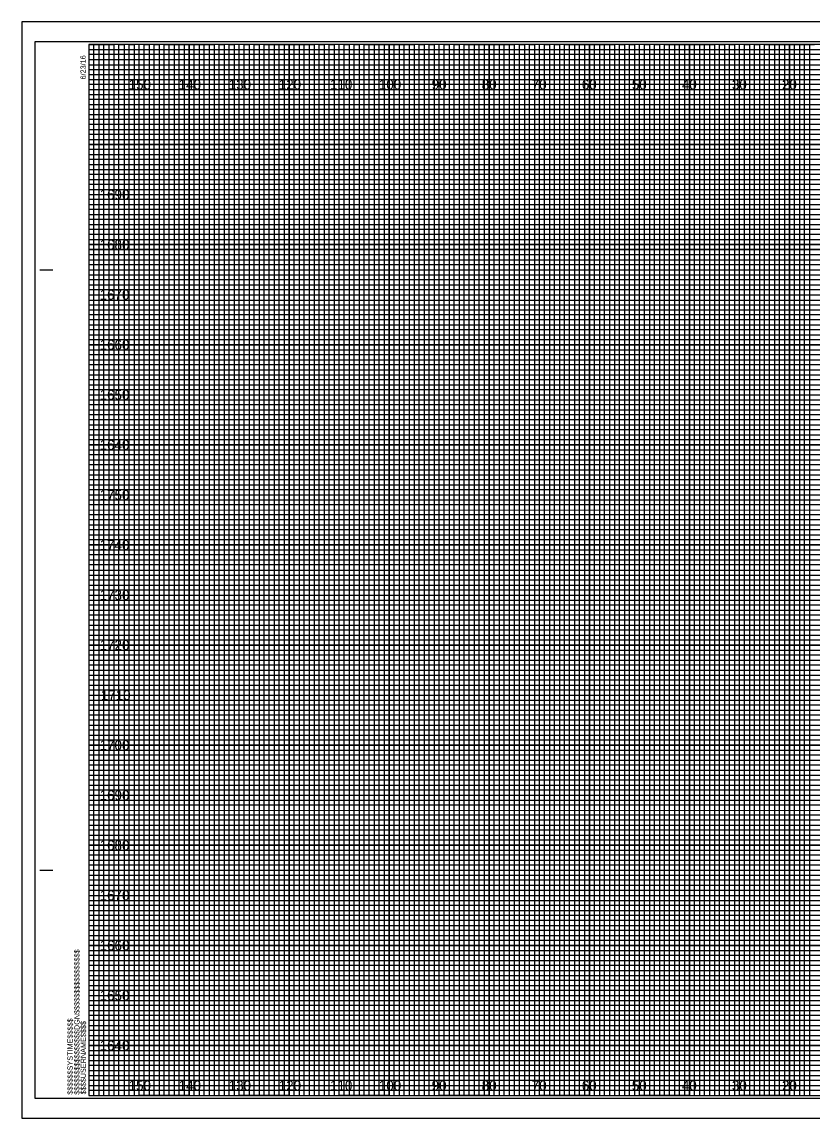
# Model space of a CAD drawing. Extents: x -13 to 323, y 655 to 874.
# Drawn here: x -13.4 to 144.5, y 655.5 to 874.5 of the extents above; entities that cross this region are included whole.
import ezdxf

# ---------------------------------------------------------------- set-up
doc = ezdxf.new("R2010")
doc.units = 0
for name, color, linetype in [('Exist Cross Section Cell', 7, 'Continuous'), ('Exist XS Center Line Elevation Label', 7, 'Continuous'), ('Exist XS Ground Line', 7, 'Continuous'), ('Prop XS Dump Level', 7, 'Continuous'), ('Prop XS Finish Grade', 7, 'Continuous'), ('Prop XS Finish Grade Earthwork', 7, 'Continuous'), ('Prop XS Pvmt Edge Slope', 7, 'Continuous'), ('Prop XS SE Text', 7, 'Continuous'), ('Prop XS SS Elevation Text', 7, 'Continuous'), ('Prop XS Subgrade Earthwork', 7, 'Continuous'), ('Scratch_Level_5', 7, 'Continuous')]:
    doc.layers.add(name, color=color, linetype=linetype)

msp = doc.modelspace()

# ---------------------------------------------------------------- linework, layer by layer
at = {"layer": 'Exist Cross Section Cell'}
for points in [[(0, 870), (5, 870), (5, 660), (15, 660), (15, 870), (25, 870), (25, 660), (35, 660), (35, 870), (45, 870), (45, 660), (55, 660), (55, 870), (65, 870), (65, 660), (75, 660), (75, 870), (85, 870), (85, 660), (95, 660), (95, 870), (105, 870), (105, 660), (115, 660), (115, 870), (125, 870), (125, 660), (135, 660), (135, 870), (145, 870)], [(0, 865), (275, 865)], [(0, 845), (320, 845), (320, 855), (0, 855)], [(0, 825), (320, 825), (320, 835), (0, 835)], [(0, 805), (320, 805), (320, 815), (0, 815)], [(0, 785), (320, 785), (320, 795), (0, 795)], [(0, 765), (320, 765), (320, 775), (0, 775)], [(0, 745), (320, 745), (320, 755), (0, 755)], [(0, 725), (320, 725), (320, 735), (0, 735)], [(0, 705), (320, 705), (320, 715), (0, 715)], [(0, 685), (320, 685), (320, 695), (0, 695)], [(0, 665), (320, 665), (320, 675), (0, 675)]]:
    msp.add_lwpolyline(points, dxfattribs=at)
at = {"layer": 'Exist XS Center Line Elevation Label'}
for p, q in [((10, 870), (0, 870)), ((10, 660), (10, 870)), ((30, 870), (20, 870)), ((20, 870), (20, 660)), ((30, 660), (30, 870)), ((50, 870), (40, 870)), ((40, 870), (40, 660)), ((50, 660), (50, 870)), ((70, 870), (60, 870)), ((60, 870), (60, 660)), ((70, 660), (70, 870)), ((90, 870), (80, 870)), ((80, 870), (80, 660)), ((90, 660), (90, 870)), ((110, 870), (100, 870)), ((100, 870), (100, 660)), ((110, 660), (110, 870)), ((130, 870), (120, 870)), ((120, 870), (120, 660)), ((130, 660), (130, 870)), ((150, 870), (140, 870)), ((140, 870), (140, 660)), ((20, 660), (10, 660)), ((40, 660), (30, 660)), ((60, 660), (50, 660)), ((80, 660), (70, 660)), ((100, 660), (90, 660)), ((120, 660), (110, 660)), ((140, 660), (130, 660))]:
    msp.add_line(p, q, dxfattribs=at)
for points in [[(0, 860), (320, 860), (320, 850), (0, 850)], [(0, 840), (320, 840), (320, 830), (0, 830)], [(0, 820), (320, 820), (320, 810), (0, 810)], [(0, 800), (320, 800), (320, 790), (0, 790)], [(0, 780), (320, 780), (320, 770), (0, 770)], [(0, 760), (320, 760), (320, 750), (0, 750)], [(0, 740), (320, 740), (320, 730), (0, 730)], [(0, 720), (320, 720), (320, 710), (0, 710)], [(0, 700), (320, 700), (320, 690), (0, 690)], [(0, 680), (320, 680), (320, 670), (0, 670)]]:
    msp.add_lwpolyline(points, dxfattribs=at)
at = {"layer": 'Prop XS Dump Level'}
for p, q in [((-9.8, 825), (-7.3, 825)), ((-9.7, 825), (-7.2, 825)), ((-9.8, 705), (-7.3, 705)), ((-9.7, 705), (-7.2, 705)), ((0, 660), (0, 660)), ((0, 660), (0, 660)), ((0, 660), (0, 660)), ((0, 660), (0, 660)), ((0, 660), (0, 660)), ((0, 660), (0, 660)), ((0, 660), (0, 660))]:
    msp.add_line(p, q, dxfattribs=at)
msp.add_lwpolyline([(320, 870), (0, 870), (0, 660), (320, 660)], close=True, dxfattribs=at)
at = {"layer": 'Prop XS Finish Grade'}
for p, q in [((323.3, 874.5), (-13.4, 874.5)), ((-13.4, 874.5), (-13.4, 655.5)), ((-13.4, 655.5), (323.3, 655.5))]:
    msp.add_line(p, q, dxfattribs=at)
at = {"layer": 'Prop XS Finish Grade Earthwork'}
msp.add_lwpolyline([(-10.8, 659.5), (322.4, 659.5), (322.4, 870.5), (-10.8, 870.5)], close=True, dxfattribs=at)
at = {"layer": 'Prop XS SE Text'}
for points in [[(0, 660), (1, 660), (1, 870), (2, 870), (2, 660)], [(2, 660), (3, 660), (3, 870), (4, 870), (4, 660)], [(5, 660), (6, 660), (6, 870), (7, 870), (7, 660)], [(7, 660), (8, 660), (8, 870), (9, 870), (9, 660)], [(10, 660), (11, 660), (11, 870), (12, 870), (12, 660)], [(12, 660), (13, 660), (13, 870), (14, 870), (14, 660)], [(15, 660), (16, 660), (16, 870), (17, 870), (17, 660)], [(17, 660), (18, 660), (18, 870), (19, 870), (19, 660)], [(20, 660), (21, 660), (21, 870), (22, 870), (22, 660)], [(22, 660), (23, 660), (23, 870), (24, 870), (24, 660)], [(25, 660), (26, 660), (26, 870), (27, 870), (27, 660)], [(27, 660), (28, 660), (28, 870), (29, 870), (29, 660)], [(30, 660), (31, 660), (31, 870), (32, 870), (32, 660)], [(32, 660), (33, 660), (33, 870), (34, 870), (34, 660)], [(35, 660), (36, 660), (36, 870), (37, 870), (37, 660)], [(37, 660), (38, 660), (38, 870), (39, 870), (39, 660)], [(40, 660), (41, 660), (41, 870), (42, 870), (42, 660)], [(42, 660), (43, 660), (43, 870), (44, 870), (44, 660)], [(45, 660), (46, 660), (46, 870), (47, 870), (47, 660)], [(47, 660), (48, 660), (48, 870), (49, 870), (49, 660)], [(50, 660), (51, 660), (51, 870), (52, 870), (52, 660)], [(52, 660), (53, 660), (53, 870), (54, 870), (54, 660)], [(55, 660), (56, 660), (56, 870), (57, 870), (57, 660)], [(57, 660), (58, 660), (58, 870), (59, 870), (59, 660)], [(60, 660), (61, 660), (61, 870), (62, 870), (62, 660)], [(62, 660), (63, 660), (63, 870), (64, 870), (64, 660)], [(65, 660), (66, 660), (66, 870), (67, 870), (67, 660)], [(67, 660), (68, 660), (68, 870), (69, 870), (69, 660)], [(70, 660), (71, 660), (71, 870), (72, 870), (72, 660)], [(72, 660), (73, 660), (73, 870), (74, 870), (74, 660)], [(75, 660), (76, 660), (76, 870), (77, 870), (77, 660)], [(77, 660), (78, 660), (78, 870), (79, 870), (79, 660)], [(80, 660), (81, 660), (81, 870), (82, 870), (82, 660)], [(82, 660), (83, 660), (83, 870), (84, 870), (84, 660)], [(85, 660), (86, 660), (86, 870), (87, 870), (87, 660)], [(87, 660), (88, 660), (88, 870), (89, 870), (89, 660)], [(90, 660), (91, 660), (91, 870), (92, 870), (92, 660)], [(92, 660), (93, 660), (93, 870), (94, 870), (94, 660)], [(95, 660), (96, 660), (96, 870), (97, 870), (97, 660)], [(97, 660), (98, 660), (98, 870), (99, 870), (99, 660)], [(100, 660), (101, 660), (101, 870), (102, 870), (102, 660)], [(102, 660), (103, 660), (103, 870), (104, 870), (104, 660)], [(105, 660), (106, 660), (106, 870), (107, 870), (107, 660)], [(107, 660), (108, 660), (108, 870), (109, 870), (109, 660)], [(110, 660), (111, 660), (111, 870), (112, 870), (112, 660)], [(112, 660), (113, 660), (113, 870), (114, 870), (114, 660)], [(115, 660), (116, 660), (116, 870), (117, 870), (117, 660)], [(117, 660), (118, 660), (118, 870), (119, 870), (119, 660)], [(120, 660), (121, 660), (121, 870), (122, 870), (122, 660)], [(122, 660), (123, 660), (123, 870), (124, 870), (124, 660)], [(125, 660), (126, 660), (126, 870), (127, 870), (127, 660)], [(127, 660), (128, 660), (128, 870), (129, 870), (129, 660)], [(130, 660), (131, 660), (131, 870), (132, 870), (132, 660)], [(132, 660), (133, 660), (133, 870), (134, 870), (134, 660)], [(135, 660), (136, 660), (136, 870), (137, 870), (137, 660)], [(137, 660), (138, 660), (138, 870), (139, 870), (139, 660)], [(140, 660), (141, 660), (141, 870), (142, 870), (142, 660)], [(142, 660), (143, 660), (143, 870), (144, 870), (144, 660)]]:
    msp.add_lwpolyline(points, dxfattribs=at)
at = {"layer": 'Prop XS SS Elevation Text'}
msp.add_lwpolyline([(-13.4, 655.5), (323.3, 655.5), (323.3, 874.5), (-13.4, 874.5)], close=True, dxfattribs=at)
at = {"layer": 'Prop XS Subgrade Earthwork'}
for p, q in [((10, 660), (10, 870)), ((20, 660), (20, 870)), ((30, 660), (30, 870)), ((40, 660), (40, 870)), ((50, 660), (50, 870)), ((60, 660), (60, 870)), ((70, 660), (70, 870)), ((80, 660), (80, 870)), ((90, 660), (90, 870)), ((100, 660), (100, 870)), ((110, 660), (110, 870)), ((120, 660), (120, 870)), ((130, 660), (130, 870)), ((140, 660), (140, 870)), ((0, 860), (320, 860)), ((0, 850), (320, 850)), ((0, 840), (320, 840)), ((0, 830), (320, 830)), ((0, 820), (320, 820)), ((0, 810), (320, 810)), ((0, 800), (320, 800)), ((0, 790), (320, 790)), ((0, 780), (320, 780)), ((0, 770), (320, 770)), ((0, 760), (320, 760)), ((0, 750), (320, 750)), ((0, 740), (320, 740)), ((0, 730), (320, 730)), ((0, 720), (320, 720)), ((0, 710), (320, 710)), ((0, 700), (320, 700)), ((0, 690), (320, 690)), ((0, 680), (320, 680)), ((0, 670), (320, 670))]:
    msp.add_line(p, q, dxfattribs=at)
at = {"layer": 'Scratch_Level_5'}
for p, q in [((0, 869), (260, 869)), ((260, 867.98), (0, 867.98)), ((0, 867.98), (0, 867)), ((0, 867), (260, 867)), ((260, 865.89), (0, 865.89)), ((0, 865.89), (0, 864)), ((0, 864), (320, 864))]:
    msp.add_line(p, q, dxfattribs=at)
for points in [[(0, 863), (270, 863), (320, 863), (320, 862), (0, 862)], [(0, 861), (320, 861), (320, 859), (0, 859)], [(0, 858), (320, 858), (320, 857), (0, 856.98)], [(0, 856), (320, 856), (320, 854), (0, 854)], [(0, 853), (320, 853), (320, 852), (0, 852)], [(0, 851), (320, 851), (320, 849), (0, 849)], [(0, 848), (320, 848), (320, 847), (0, 847)], [(0, 846), (320, 846), (320, 844), (0, 844)], [(0, 843), (320, 843), (320, 842), (0, 842)], [(0, 841), (320, 841), (320, 839), (0, 839)], [(0, 838), (320, 838), (320, 837), (0, 837)], [(0, 836), (320, 836), (320, 833.95), (320, 833), (320, 832), (0, 832)], [(0, 834), (320, 834), (320, 833), (0, 833)], [(0, 831), (320, 831), (320, 829), (0, 829.03)], [(0, 829.03), (320, 829), (320, 828), (0, 828)], [(0, 827), (320, 827), (320, 826), (0, 826)], [(0, 824), (320, 824), (320, 823), (0, 823)], [(0, 822), (320, 822), (320, 821), (0, 821)], [(-0.07, 818.89), (320, 818.89), (320, 817.88), (-0.07, 817.88)], [(0, 817), (320, 817), (320, 816), (0, 816)], [(0, 814), (320, 814), (320, 813), (0, 813)], [(0, 812), (320, 812), (320, 811), (0, 811)], [(0, 809), (320, 809), (320, 808), (0, 808)], [(0, 807), (320, 807), (320, 806), (0, 806)], [(0, 804), (320, 804), (320, 803), (0, 803)], [(0, 802), (320, 802), (320, 801), (0, 801)], [(0, 799), (320, 799), (319.99, 797.98), (0, 798)], [(0, 797), (320, 797), (320, 796), (0, 796)], [(0, 794), (320, 794), (320, 793), (0, 793)], [(0, 792), (320, 792), (320, 791), (0, 791)], [(0, 789), (320, 789), (320, 788), (0, 788)], [(0, 787), (320, 787), (320, 786), (0, 786)], [(0, 784), (320, 784), (320, 783), (0, 783)], [(0, 782), (320, 782), (320, 781), (0, 781)], [(0, 779), (320, 779), (320, 778), (0, 778)], [(0, 776.99), (320.07, 776.91), (320, 776), (0, 776)], [(0, 774), (320, 774), (320, 773), (0, 773)], [(0, 772), (320, 772), (320, 771), (0, 771)], [(0, 769), (320, 769), (320, 768), (0, 768)], [(0, 767), (320, 767), (320, 766), (0, 766)], [(0, 764), (320, 764), (320, 763), (0, 763)], [(0, 762), (320, 762), (320, 761), (0, 761)], [(0, 759), (320, 759), (320, 758), (0, 758)], [(0, 757), (320, 757), (320, 756), (0, 756)], [(0, 754), (320, 754), (320, 753), (0, 753)], [(0, 752), (320, 752), (320, 751), (0, 751)], [(0, 749), (320, 749), (320, 748), (0, 748)], [(0, 747), (320, 747), (320, 746), (0, 746)], [(0, 744), (320, 744), (320, 743), (0, 743)], [(0, 742), (320, 742), (320, 741), (0, 741)], [(0, 739), (320, 739), (319.99, 737.98), (0, 738)], [(0, 737), (320, 737), (320, 736), (0, 736)], [(0, 734), (320, 734), (320, 733), (0, 733)], [(0, 732), (320, 732), (320, 731), (0, 731)], [(0, 729), (320, 729), (320, 728), (0, 728)], [(0, 727), (320, 727), (320, 726), (0, 726)], [(0, 724), (320, 724), (320, 723), (0, 723)], [(0, 722), (320, 722), (320, 721), (0, 721)], [(0, 719), (320, 719), (320, 718), (0, 718)], [(0, 716.99), (320.07, 716.91), (320, 716), (0, 716)], [(0, 714), (320, 714), (320, 713), (0, 713)], [(0, 712), (320, 712), (320, 711), (0, 711)], [(0, 709), (320, 709), (320, 708), (0, 708)], [(0, 707), (320, 707), (320, 706), (0, 706)], [(0, 704), (320, 704), (320, 703), (0, 703)], [(0, 702), (320, 702), (320, 701), (0, 701)], [(0, 699), (320, 699), (320, 698), (0, 698)], [(0, 697), (320, 697), (320, 696), (0, 696)], [(0, 694), (320, 694), (320, 693), (0, 693)], [(0, 692), (320, 692), (320, 691), (0, 691)], [(0, 689), (320, 689), (320, 688), (0, 688)], [(0, 687), (320, 687), (320, 686), (0, 686)], [(0, 684), (320, 684), (320, 683), (0, 683)], [(0, 682), (320, 682), (320, 681), (0, 681)], [(0, 679), (320, 679), (320, 678), (0, 678)], [(0, 677), (320, 677), (320, 676), (0, 676)], [(0, 674), (320, 674), (320, 673), (0, 673)], [(0, 672), (320, 672), (320, 671), (0, 671)], [(0, 669), (320, 669), (320, 668), (0, 668)], [(0, 667), (320, 667), (320, 666), (0, 666)], [(0, 664), (320, 664), (320, 663), (0, 663)], [(0, 662), (320, 662), (320, 661), (0, 661)]]:
    msp.add_lwpolyline(points, dxfattribs=at)

# ---------------------------------------------------------------- texts
at = {"layer": 'Exist XS Ground Line'}
for s, p in [('150', (7.93, 861)), ('140', (17.93, 861)), ('130', (27.93, 861)), ('120', (37.93, 861)), ('110', (48.17, 861)), ('100', (57.93, 861)), ('90', (68.48, 861)), ('80', (78.48, 861)), ('70', (88.48, 861)), ('60', (98.48, 861)), ('50', (108.48, 861)), ('40', (118.48, 861)), ('30', (128.48, 861)), ('20', (138.48, 861)), ('150', (7.93, 661)), ('140', (17.93, 661)), ('130', (27.93, 661)), ('120', (37.93, 661)), ('110', (48.17, 661)), ('100', (57.93, 661)), ('90', (68.48, 661)), ('80', (78.48, 661)), ('70', (88.48, 661)), ('60', (98.48, 661)), ('50', (108.48, 661)), ('40', (118.48, 661)), ('30', (128.48, 661)), ('20', (138.48, 661))]:
    msp.add_text(s, height=2, dxfattribs=at).set_placement(p)
at = {"layer": 'Prop XS Dump Level'}
for s, p in [('6/23/16', (-0.65, 863)), ('$$$$$$$$$$$$$$$$DGN$$$$$$$$$$$$$$$$', (-1.88, 660.18)), ('$$$$$$SYSTIME$$$$$', (-3.26, 660.18)), ('$$$$USERNAME$$$$', (-0.62, 660.23))]:
    msp.add_text(s, height=1.05, rotation=90, dxfattribs=at).set_placement(p)
at = {"layer": 'Prop XS Pvmt Edge Slope'}
for s, p in [('1690', (2.13, 839)), ('1680', (2.13, 829)), ('1670', (2.13, 819)), ('1660', (2.13, 809)), ('1650', (2.13, 799)), ('1640', (2.13, 789)), ('1750', (2.13, 779)), ('1740', (2.13, 769)), ('1730', (2.13, 759)), ('1720', (2.13, 749)), ('1710', (2.37, 739)), ('1700', (2.13, 729)), ('1690', (2.13, 719)), ('1680', (2.13, 709)), ('1670', (2.13, 699)), ('1660', (2.13, 689)), ('1650', (2.13, 679)), ('1640', (2.13, 669))]:
    msp.add_text(s, height=2, dxfattribs=at).set_placement(p)

doc.saveas('drawing.dxf')
